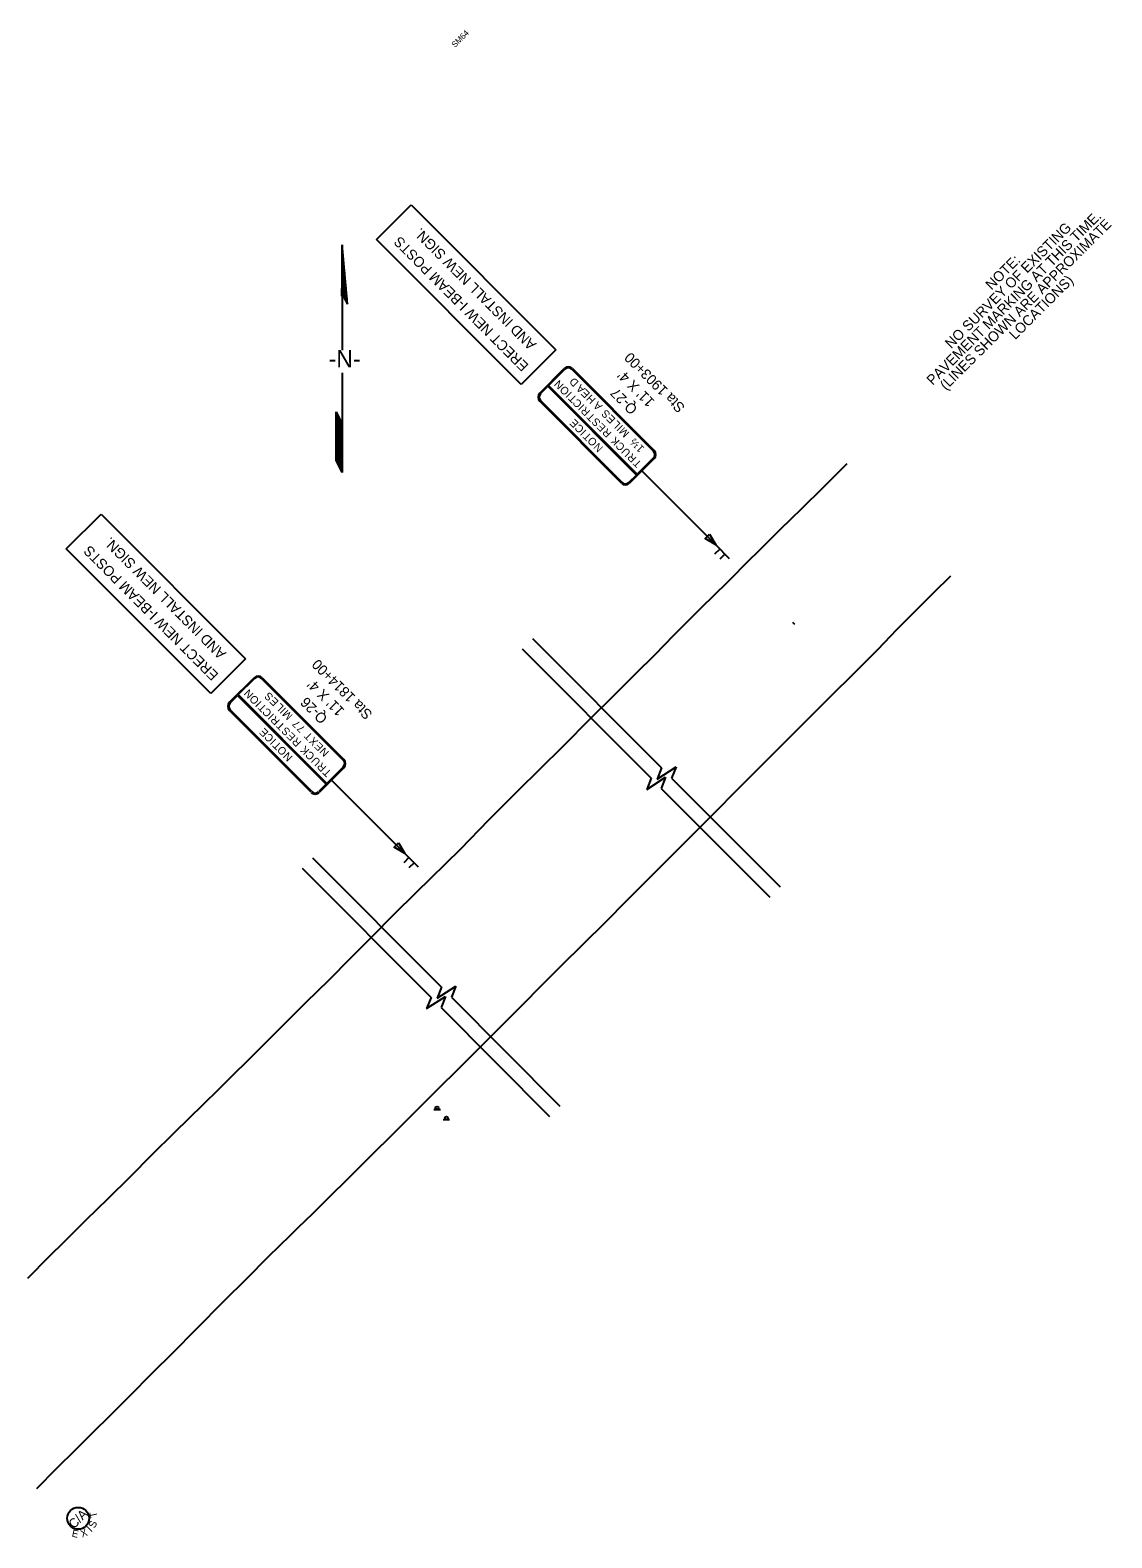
# Model space of a CAD drawing. Extents: x 1825735 to 1827318, y 1193725 to 1195507.
# Drawn here: x 1826577 to 1827318, y 1194474 to 1195507 of the extents above; entities that cross this region are included whole.
import ezdxf

# ---------------------------------------------------------------- set-up
doc = ezdxf.new("R2010")
doc.units = 0
for name, color, linetype in [('RD_EX_Road', 7, 'Continuous'), ('RD_PD_Final_TX', 7, 'Continuous'), ('RD_SHT_MatchLine', 7, 'Continuous'), ('RD_SHT_TX', 7, 'Continuous'), ('RD_Sketch1', 7, 'Continuous'), ('RD_Sketch8', 7, 'Continuous'), ('SN_P_Signs', 7, 'Continuous')]:
    doc.layers.add(name, color=color, linetype=linetype)

msp = doc.modelspace()

# ---------------------------------------------------------------- linework, layer by layer
at = {"layer": 'RD_EX_Road'}
for points in [[(1827136.5, 1195209.8), (1827134.8, 1195208.1), (1827120.1, 1195193.5), (1827105.3, 1195179), (1827090.8, 1195164.8), (1827078.6, 1195152.8), (1827066.2, 1195140.3), (1827058.5, 1195132.6), (1827054.4, 1195128.4), (1827036.5, 1195110.9), (1827021.7, 1195096.1), (1827017.8, 1195092.1), (1827004.9, 1195078.9), (1826991.8, 1195065.9), (1826976.7, 1195050.8), (1826961.2, 1195035.6), (1826941.7, 1195015.9), (1826926.5, 1195000.9), (1826911.3, 1194985.8), (1826901.3, 1194976), (1826891.1, 1194965.8), (1826871.9, 1194945.9), (1826851.4, 1194925.8), (1826841.4, 1194916), (1826826.3, 1194901.1), (1826811.2, 1194885.9), (1826796.6, 1194871.3), (1826781.6, 1194855.9), (1826766.2, 1194841), (1826751.3, 1194826), (1826736.3, 1194810.9), (1826726.1, 1194800.9), (1826716.1, 1194791.1), (1826706, 1194781.2), (1826695.9, 1194771.1), (1826686, 1194761.4), (1826675.9, 1194751.7), (1826660.7, 1194736.6), (1826645.7, 1194721.4), (1826630.6, 1194706.5), (1826615.6, 1194691.8), (1826600.8, 1194677), (1826590.2, 1194666.7), (1826575.7, 1194652)], [(1826582, 1194508.1), (1826595.5, 1194521.7), (1826608.8, 1194535), (1826622.2, 1194548.3), (1826630.6, 1194556.5), (1826645.8, 1194571.7), (1826660.6, 1194586.8), (1826675.8, 1194601.8), (1826690.6, 1194616.8), (1826710.4, 1194636.9), (1826725.4, 1194651.7), (1826740.5, 1194667), (1826755.6, 1194681.6), (1826760.9, 1194686.9), (1826771, 1194696.5), (1826781.1, 1194706.6), (1826796, 1194721.3), (1826811, 1194736.3), (1826826, 1194751.3), (1826840.8, 1194765.9), (1826856.3, 1194781.3), (1826871.4, 1194796.2), (1826886.4, 1194811.3), (1826901.3, 1194826.2), (1826916.1, 1194841), (1826926, 1194851.1), (1826941.2, 1194866.2), (1826956.1, 1194881.1), (1826971.2, 1194896), (1826986.2, 1194911.1), (1826996.1, 1194921.1), (1827006.4, 1194931.3), (1827021, 1194946), (1827031.2, 1194956.1), (1827046.3, 1194971.2), (1827061.2, 1194986.2), (1827076.2, 1195001.4), (1827104.9, 1195030.1), (1827106.4, 1195031.6), (1827126, 1195051.1), (1827141.3, 1195066.2), (1827153.6, 1195078.6), (1827157.6, 1195082.6), (1827170.9, 1195096.6), (1827180.9, 1195106.5), (1827196, 1195121.7), (1827207.6, 1195133)]]:
    msp.add_lwpolyline(points, dxfattribs=at)
at = {"layer": 'RD_SHT_MatchLine'}
for p, q in [((1826914.2, 1195083), (1827002.5, 1194994.4)), ((1826921.2, 1195090.1), (1827009.6, 1195001.5)), ((1827006.5, 1194993.9), (1827019.5, 1195002.2)), ((1827009.6, 1195001.5), (1827006.5, 1194993.9)), ((1827019.5, 1195002.2), (1827016.4, 1194994.6)), ((1826999.5, 1194986.8), (1827012.4, 1194995.1)), ((1827002.5, 1194994.4), (1826999.5, 1194986.8)), ((1827012.4, 1194995.1), (1827009.4, 1194987.5)), ((1827016.4, 1194994.6), (1827090.7, 1194920.1)), ((1827009.4, 1194987.5), (1827083.6, 1194913.1)), ((1826770.6, 1194940), (1826858.9, 1194851.4)), ((1826763.5, 1194932.9), (1826851.9, 1194844.3)), ((1826855.9, 1194843.8), (1826868.8, 1194852)), ((1826858.9, 1194851.4), (1826855.9, 1194843.8)), ((1826868.8, 1194852), (1826865.8, 1194844.5)), ((1826848.8, 1194836.7), (1826861.8, 1194845)), ((1826851.9, 1194844.3), (1826848.8, 1194836.7)), ((1826861.8, 1194845), (1826858.7, 1194837.4)), ((1826858.7, 1194837.4), (1826933, 1194762.9)), ((1826865.8, 1194844.5), (1826940, 1194770))]:
    msp.add_line(p, q, dxfattribs=at)
at = {"layer": 'RD_Sketch1'}
for p, q in [((1826790.9, 1195359.7), (1826790.7, 1195324.5)), ((1826794.7, 1195319), (1826790.9, 1195359.7)), ((1826790.9, 1195324.8), (1826790.9, 1195303)), ((1826791.2, 1195325.9), (1826794.7, 1195319)), ((1826790.9, 1195303), (1826790.9, 1195287.5)), ((1826790.9, 1195272.1), (1826790.9, 1195246.3)), ((1826786.9, 1195231.2), (1826786.9, 1195245.4)), ((1826786.9, 1195245.4), (1826790.9, 1195236.9)), ((1826790.9, 1195246.3), (1826790.9, 1195203.8)), ((1826786.9, 1195212.3), (1826786.9, 1195231.2)), ((1826790.9, 1195203.8), (1826786.9, 1195212.3))]:
    msp.add_line(p, q, dxfattribs=at)
for points in [[(1826790.9, 1195325.1), (1826790.9, 1195359.6)], [(1826791, 1195325.4), (1826791, 1195358.5)], [(1826791.1, 1195325.6), (1826791.1, 1195357.5)], [(1826791.2, 1195325.9), (1826791.2, 1195356.5)], [(1826791.3, 1195325.8), (1826791.3, 1195355.4)], [(1826791.4, 1195325.6), (1826791.4, 1195354.4)], [(1826791.5, 1195325.4), (1826791.5, 1195353.4)], [(1826791.6, 1195325.2), (1826791.6, 1195352.3)], [(1826791.7, 1195325), (1826791.7, 1195351.3)], [(1826790.9, 1195324.9), (1826790.9, 1195345.7)], [(1826791.8, 1195324.8), (1826791.8, 1195350.3)], [(1826791.9, 1195324.6), (1826791.9, 1195349.2)], [(1826792, 1195324.4), (1826792, 1195348.2)], [(1826792.1, 1195324.2), (1826792.1, 1195347.2)], [(1826792.2, 1195324), (1826792.2, 1195346.1)], [(1826792.3, 1195323.8), (1826792.3, 1195345.1)], [(1826792.4, 1195323.6), (1826792.4, 1195344.1)], [(1826792.5, 1195323.5), (1826792.5, 1195343)], [(1826792.6, 1195323.3), (1826792.6, 1195342)], [(1826792.7, 1195323.1), (1826792.7, 1195341)], [(1826792.7, 1195322.9), (1826792.7, 1195340)], [(1826792.8, 1195322.7), (1826792.8, 1195338.9)], [(1826792.9, 1195322.5), (1826792.9, 1195337.9)], [(1826793, 1195322.3), (1826793, 1195336.9)], [(1826793.1, 1195322.1), (1826793.1, 1195335.8)], [(1826793.2, 1195321.9), (1826793.2, 1195334.8)], [(1826793.3, 1195321.7), (1826793.3, 1195333.8)], [(1826793.4, 1195321.5), (1826793.4, 1195332.7)], [(1826793.5, 1195321.3), (1826793.5, 1195331.7)], [(1826793.6, 1195321.2), (1826793.6, 1195330.7)], [(1826790.8, 1195324.6), (1826790.8, 1195329.7)], [(1826793.7, 1195321), (1826793.7, 1195329.6)], [(1826793.8, 1195320.8), (1826793.8, 1195328.6)], [(1826793.9, 1195320.6), (1826793.9, 1195327.6)], [(1826794, 1195320.4), (1826794, 1195326.5)], [(1826794.1, 1195320.2), (1826794.1, 1195325.5)], [(1826794.2, 1195320), (1826794.2, 1195324.5)], [(1826794.3, 1195319.8), (1826794.3, 1195323.4)], [(1826794.4, 1195319.6), (1826794.4, 1195322.4)], [(1826794.4, 1195319.4), (1826794.4, 1195321.4)], [(1826794.5, 1195319.2), (1826794.5, 1195320.3)], [(1826794.6, 1195319), (1826794.6, 1195319.3)], [(1826787, 1195212.2), (1826787, 1195245.3)], [(1826787.1, 1195212), (1826787.1, 1195245.1)], [(1826787.2, 1195211.8), (1826787.2, 1195244.8)], [(1826787.3, 1195211.6), (1826787.3, 1195244.6)], [(1826787.4, 1195211.4), (1826787.4, 1195244.4)], [(1826787.5, 1195211.2), (1826787.5, 1195244.2)], [(1826787.6, 1195211), (1826787.6, 1195244)], [(1826787.7, 1195210.8), (1826787.7, 1195243.8)], [(1826787.8, 1195210.6), (1826787.8, 1195243.6)], [(1826787.9, 1195210.4), (1826787.9, 1195243.4)], [(1826788, 1195210.2), (1826788, 1195243.2)], [(1826788.1, 1195210), (1826788.1, 1195243)], [(1826788.2, 1195209.8), (1826788.2, 1195242.8)], [(1826788.3, 1195209.5), (1826788.3, 1195242.6)], [(1826788.3, 1195209.3), (1826788.3, 1195242.4)], [(1826788.4, 1195209.1), (1826788.4, 1195242.2)], [(1826788.5, 1195208.9), (1826788.5, 1195242)], [(1826788.6, 1195208.7), (1826788.6, 1195241.8)], [(1826788.7, 1195208.5), (1826788.7, 1195241.6)], [(1826788.8, 1195208.3), (1826788.8, 1195241.4)], [(1826788.9, 1195208.1), (1826788.9, 1195241.2)], [(1826789, 1195207.9), (1826789, 1195241)], [(1826789.1, 1195207.7), (1826789.1, 1195240.8)], [(1826789.2, 1195207.5), (1826789.2, 1195240.6)], [(1826789.3, 1195207.3), (1826789.3, 1195240.4)], [(1826789.4, 1195207.1), (1826789.4, 1195240.2)], [(1826789.5, 1195206.9), (1826789.5, 1195240)], [(1826789.6, 1195206.7), (1826789.6, 1195239.8)], [(1826789.7, 1195206.5), (1826789.7, 1195239.6)], [(1826789.8, 1195206.3), (1826789.8, 1195239.4)], [(1826789.9, 1195206.1), (1826789.9, 1195239.2)], [(1826790, 1195205.9), (1826790, 1195239)], [(1826790, 1195205.7), (1826790, 1195238.8)], [(1826790.1, 1195205.5), (1826790.1, 1195238.6)], [(1826790.2, 1195205.3), (1826790.2, 1195238.4)], [(1826790.3, 1195205.1), (1826790.3, 1195238.2)], [(1826790.4, 1195204.9), (1826790.4, 1195238)], [(1826790.5, 1195204.7), (1826790.5, 1195237.8)], [(1826790.6, 1195204.5), (1826790.6, 1195237.6)], [(1826790.7, 1195204.3), (1826790.7, 1195237.4)], [(1826790.8, 1195204.1), (1826790.8, 1195237.1)], [(1826790.9, 1195203.9), (1826790.9, 1195236.9)]]:
    msp.add_lwpolyline(points, dxfattribs=at)
at = {"layer": 'RD_Sketch8'}
msp.add_circle((1826610.3, 1194487.7), 7.5, dxfattribs=at)
at = {"layer": 'SN_P_Signs'}
for p, q in [((1826814.5, 1195363.3), (1826838.3, 1195387)), ((1826838.3, 1195387), (1826937.2, 1195287.9)), ((1826913.4, 1195264.1), (1826814.5, 1195363.3)), ((1826937.2, 1195287.9), (1826913.4, 1195264.1)), ((1826926.2, 1195258.2), (1826943, 1195275)), ((1826943.5, 1195274.5), (1826932.3, 1195263.4)), ((1827004.5, 1195213.3), (1826987.7, 1195196.5)), ((1826992.8, 1195202.6), (1827004.1, 1195213.8)), ((1826992.4, 1195202.1), (1826987.2, 1195197)), ((1826996.1, 1195204.9), (1827046.7, 1195154.2)), ((1826602.1, 1195151.6), (1826626, 1195175.3)), ((1826626, 1195175.3), (1826724.8, 1195076.2)), ((1826701, 1195052.4), (1826602.1, 1195151.6)), ((1827049.4, 1195151.4), (1827045.9, 1195147.9)), ((1827046.7, 1195154.2), (1827055.9, 1195145)), ((1827053, 1195147.9), (1827049.4, 1195144.4)), ((1827100.9, 1195099.8), (1827099.5, 1195101.2)), ((1826724.8, 1195076.2), (1826701, 1195052.4)), ((1826713.8, 1195046.5), (1826730.7, 1195063.3)), ((1826719.9, 1195051.7), (1826731.1, 1195062.9)), ((1826714.3, 1195046.1), (1826719.4, 1195051.2)), ((1826719.4, 1195051.2), (1826780, 1194990.4)), ((1826780.5, 1194990.9), (1826719.9, 1195051.7)), ((1826792.2, 1195001.6), (1826775.3, 1194984.8)), ((1826791.7, 1195002.1), (1826780.5, 1194990.9)), ((1826780, 1194990.4), (1826774.9, 1194985.3)), ((1826783.7, 1194993.2), (1826833.9, 1194942.9)), ((1826800.2, 1194976.7), (1826833.9, 1194942.9)), ((1826836.6, 1194940.2), (1826833.1, 1194936.6)), ((1826836.6, 1194940.2), (1826833.1, 1194936.6)), ((1826833.9, 1194942.9), (1826843.1, 1194933.7)), ((1826833.9, 1194942.9), (1826843.1, 1194933.7)), ((1826840.2, 1194936.6), (1826836.7, 1194933.1)), ((1826840.2, 1194936.6), (1826836.7, 1194933.1)), ((1826853.7, 1194767.7), (1826858.2, 1194767.7)), ((1826860, 1194760.8), (1826864.5, 1194760.8))]:
    msp.add_line(p, q, dxfattribs=at)
for points in [[(1827004.1, 1195218.4), (1826948.2, 1195274.5)], [(1826948.6, 1195275), (1827004.5, 1195218.9)], [(1826926.7, 1195257.8), (1826931.8, 1195262.9)], [(1826931.8, 1195262.9), (1826992.4, 1195202.1)], [(1826932.3, 1195263.4), (1826992.8, 1195202.6)], [(1826982.1, 1195196.5), (1826926.2, 1195252.6)], [(1826982.6, 1195197), (1826926.7, 1195253.1)], [(1826735.8, 1195062.8), (1826791.7, 1195006.8)], [(1826736.3, 1195063.3), (1826792.2, 1195007.2)], [(1826769.7, 1194984.9), (1826713.8, 1195040.9)], [(1826770.2, 1194985.3), (1826714.3, 1195041.4)]]:
    msp.add_lwpolyline(points, dxfattribs=at)
for points in [[(1827042.3, 1195161.5), (1827046.7, 1195154.2), (1827039.4, 1195158.6)], [(1826829.5, 1194950.2), (1826833.9, 1194942.9), (1826826.6, 1194947.3)], [(1826829.5, 1194950.2), (1826833.9, 1194942.9), (1826826.6, 1194947.3)]]:
    msp.add_lwpolyline(points, close=True, dxfattribs=at)
for centre in [(1826855.9, 1194768.7), (1826862.3, 1194761.8)]:
    msp.add_circle(centre, 1, dxfattribs=at)
for centre, radius, start, end in [((1826945.8, 1195272.2), 3.96, 44.9091, 134.9091), ((1826945.8, 1195272.2), 3.3, 44.9091, 134.9091), ((1826929, 1195255.4), 3.96, 134.9091, 224.9091), ((1826929, 1195255.4), 3.3, 134.9091, 224.9091), ((1827001.7, 1195216.1), 3.3, 314.9091, 44.9091), ((1827001.7, 1195216.1), 3.96, 314.9091, 44.9091), ((1826984.9, 1195199.3), 3.96, 224.9091, 314.9091), ((1826984.9, 1195199.3), 3.3, 224.9091, 314.9091), ((1826733.5, 1195060.5), 3.96, 44.9091, 134.9091), ((1826733.5, 1195060.5), 3.3, 44.9091, 134.9091), ((1826716.6, 1195043.7), 3.96, 134.9091, 224.9091), ((1826716.6, 1195043.7), 3.3, 134.9091, 224.9091), ((1826789.4, 1195004.4), 3.3, 314.9091, 44.9091), ((1826789.4, 1195004.4), 3.96, 314.9091, 44.9091), ((1826772.5, 1194987.6), 3.96, 224.9091, 314.9091), ((1826772.5, 1194987.6), 3.3, 224.9091, 314.9091)]:
    msp.add_arc(centre, radius, start, end, dxfattribs=at)

# ---------------------------------------------------------------- texts
at = {"layer": 'RD_PD_Final_TX'}
for s, p in [('PAVEMENT MARKING AT THIS TIME.', (1827195.2, 1195263.1)), ('(LINES SHOWN ARE APPROXIMATE', (1827204.3, 1195259.7)), ('NO SURVEY OF EXISTING', (1827207.8, 1195288.2)), ('NOTE:', (1827235.5, 1195328.4)), ('LOCATIONS)', (1827251.6, 1195294.3))]:
    msp.add_text(s, height=7, rotation=44.9091, dxfattribs=at).set_placement(p)
at = {"layer": 'RD_SHT_TX'}
msp.add_text('SM64', height=4, rotation=44.9091, dxfattribs=at).set_placement((1826868.2, 1195494.5))
at = {"layer": 'RD_Sketch1'}
msp.add_text('-N-', height=11.81, rotation=0, dxfattribs=at).set_placement((1826781.7, 1195275.8))
at = {"layer": 'RD_Sketch8'}
for s, height, rotation, p in [('C/A', 6.25, 44.9091, (1826607.4, 1194480.2)), ('S', 5, 66.7015, (1826621.7, 1194480.6)), ('T', 5, 103.0943, (1826623.7, 1194488.7)), ('E', 5, 348.1204, (1826605.6, 1194475.2)), ('X', 5, 20.5497, (1826613, 1194474.5)), ('I', 5, 44.7097, (1826619.2, 1194477.9))]:
    msp.add_text(s, height=height, rotation=rotation, dxfattribs=at).set_placement(p)
at = {"layer": 'SN_P_Signs'}
for s, height, rotation, p in [('ERECT NEW I-BEAM POSTS', 7, 134.9092, (1826919.1, 1195277.3)), ('AND INSTALL NEW SIGN.', 7, 134.9092, (1826924.3, 1195291.9)), ('Sta 1903+00', 7, 134.9092, (1827026.1, 1195248.9)), ("11' X 4'", 7, 134.9092, (1827005.3, 1195252.8)), ('N', 5.28, 134.9091, (1826942.9, 1195263.9)), ('O', 5.28, 134.9091, (1826947, 1195259.8)), ('I', 5.28, 134.9091, (1826948.6, 1195258.2)), ('D', 5.28, 134.9091, (1826953.3, 1195265.7)), ('A', 5.28, 134.9091, (1826957.7, 1195261.2)), ('E', 5.28, 134.9091, (1826961, 1195257.9)), ('Q-27', 7, 134.9092, (1826993.6, 1195247.7)), ('T', 5.28, 134.9091, (1826952.1, 1195254.7)), ('C', 5.28, 134.9091, (1826955.6, 1195251.2)), ('I', 5.28, 134.9091, (1826957.2, 1195249.6)), ('R', 5.28, 134.9091, (1826961.1, 1195245.7)), ('H', 5.28, 134.9091, (1826964.9, 1195254)), ('A', 5.28, 134.9091, (1826969.4, 1195249.5)), ('E', 5.28, 134.9091, (1826953.3, 1195237.6)), ('E', 5.28, 134.9091, (1826953.3, 1195237.6)), ('T', 5.28, 134.9091, (1826964.6, 1195242.1)), ('S', 5.28, 134.9091, (1826968.3, 1195238.4)), ('E', 5.28, 134.9091, (1826971.8, 1195234.9)), ('S', 5.28, 134.9091, (1826974.9, 1195244)), ('E', 5.28, 134.9091, (1826978.4, 1195240.5)), ('L', 5.28, 134.9091, (1826981.9, 1195237)), ('C', 5.28, 134.9091, (1826957, 1195233.9)), ('C', 5.28, 134.9091, (1826957, 1195233.9)), ('I', 5.28, 134.9091, (1826958.6, 1195232.3)), ('I', 5.28, 134.9091, (1826958.6, 1195232.3)), ('T', 5.28, 134.9091, (1826962.1, 1195228.7)), ('T', 5.28, 134.9091, (1826962.1, 1195228.7)), ('O', 5.28, 134.9091, (1826966, 1195224.9)), ('O', 5.28, 134.9091, (1826966, 1195224.9)), ('R', 5.28, 134.9091, (1826975.8, 1195230.9)), ('K', 5.28, 134.9091, (1826981.3, 1195225.4)), ('I', 5.28, 134.9091, (1826983.5, 1195235.4)), ('M', 5.28, 134.9091, (1826987.9, 1195231)), ('½', 5.28, 134.9091, (1826995.2, 1195223.6)), ('N', 5.28, 134.9091, (1826969.9, 1195220.9)), ('N', 5.28, 134.9091, (1826969.9, 1195220.9)), ('C', 5.28, 134.9091, (1826985, 1195221.7)), ('U', 5.28, 134.9091, (1826988.9, 1195217.7)), ('R', 5.28, 134.9091, (1826992.9, 1195213.8)), ('1', 5.28, 134.9091, (1826998.2, 1195220.6)), ('T', 5.28, 134.9091, (1826996.4, 1195210.3)), ('AND INSTALL NEW SIGN.', 7, 134.9092, (1826712, 1195080.2)), ('ERECT NEW I-BEAM POSTS', 7, 134.9092, (1826706.8, 1195065.6)), ('Sta 1814+00', 7, 134.9092, (1826812.2, 1195038.8)), ('N', 5.28, 134.9091, (1826730.6, 1195052.2)), ('S', 5.28, 134.9091, (1826744.3, 1195050.5)), ('S', 5.28, 134.9091, (1826744.3, 1195050.5)), ("11' X 4'", 7, 134.9092, (1826793, 1195041.1)), ('O', 5.28, 134.9091, (1826734.6, 1195048.1)), ('I', 5.28, 134.9091, (1826736.2, 1195046.5)), ('T', 5.28, 134.9091, (1826739.7, 1195043)), ('C', 5.28, 134.9091, (1826743.2, 1195039.5)), ('E', 5.28, 134.9091, (1826747.9, 1195047)), ('E', 5.28, 134.9091, (1826747.9, 1195047)), ('L', 5.28, 134.9091, (1826751.4, 1195043.5)), ('L', 5.28, 134.9091, (1826751.4, 1195043.5)), ('I', 5.28, 134.9091, (1826753, 1195041.9)), ('I', 5.28, 134.9091, (1826753, 1195041.9)), ('Q-26', 7, 134.9092, (1826781.4, 1195035.9)), ('I', 5.28, 134.9091, (1826744.8, 1195037.9)), ('R', 5.28, 134.9091, (1826748.7, 1195034)), ('T', 5.28, 134.9091, (1826752.2, 1195030.5)), ('M', 5.28, 134.9091, (1826757.4, 1195037.5)), ('M', 5.28, 134.9091, (1826757.4, 1195037.5)), ('7', 5.28, 134.9091, (1826762.8, 1195032)), ('7', 5.28, 134.9091, (1826762.8, 1195032)), ('E', 5.28, 134.9091, (1826740.9, 1195025.9)), ('E', 5.28, 134.9091, (1826740.9, 1195025.9)), ('C', 5.28, 134.9091, (1826744.6, 1195022.2)), ('C', 5.28, 134.9091, (1826744.6, 1195022.2)), ('I', 5.28, 134.9091, (1826746.2, 1195020.6)), ('I', 5.28, 134.9091, (1826746.2, 1195020.6)), ('S', 5.28, 134.9091, (1826756, 1195026.7)), ('E', 5.28, 134.9091, (1826759.5, 1195023.2)), ('R', 5.28, 134.9091, (1826763.4, 1195019.2)), ('7', 5.28, 134.9091, (1826766, 1195028.8)), ('7', 5.28, 134.9091, (1826766, 1195028.8)), ('T', 5.28, 134.9091, (1826771.2, 1195023.6)), ('X', 5.28, 134.9091, (1826774.9, 1195019.8)), ('T', 5.28, 134.9091, (1826749.8, 1195017.1)), ('T', 5.28, 134.9091, (1826749.8, 1195017.1)), ('O', 5.28, 134.9091, (1826753.6, 1195013.2)), ('O', 5.28, 134.9091, (1826753.6, 1195013.2)), ('N', 5.28, 134.9091, (1826757.5, 1195009.2)), ('N', 5.28, 134.9091, (1826757.5, 1195009.2)), ('K', 5.28, 134.9091, (1826768.9, 1195013.7)), ('K', 5.28, 134.9091, (1826768.9, 1195013.7)), ('C', 5.28, 134.9091, (1826772.6, 1195010)), ('C', 5.28, 134.9091, (1826772.6, 1195010)), ('E', 5.28, 134.9091, (1826778.5, 1195016.3)), ('N', 5.28, 134.9091, (1826782.4, 1195012.4)), ('U', 5.28, 134.9091, (1826776.6, 1195006)), ('U', 5.28, 134.9091, (1826776.6, 1195006)), ('R', 5.28, 134.9091, (1826780.5, 1195002.1)), ('R', 5.28, 134.9091, (1826780.5, 1195002.1)), ('T', 5.28, 134.9091, (1826784, 1194998.6)), ('T', 5.28, 134.9091, (1826784, 1194998.6))]:
    msp.add_text(s, height=height, rotation=rotation, dxfattribs=at).set_placement(p)

doc.saveas('drawing.dxf')
